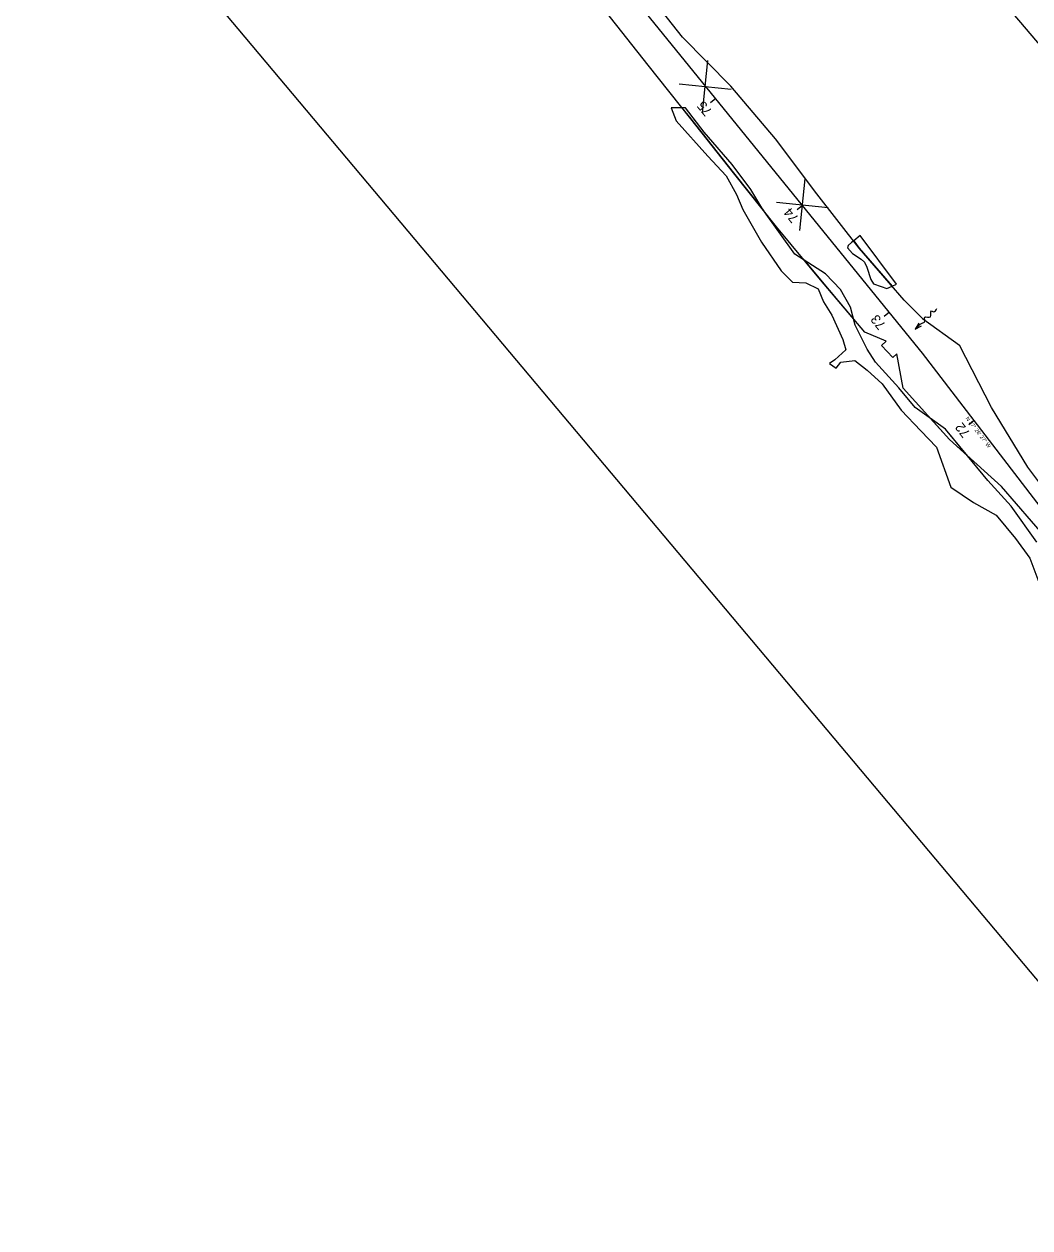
# Model space of a CAD drawing. Extents: x 2399886 to 2513208, y 556821 to 592417.
# Drawn here: x 2441599 to 2442329, y 558741 to 559616 of the extents above; entities that cross this region are included whole.
import ezdxf

# ---------------------------------------------------------------- set-up
doc = ezdxf.new("R2010")
doc.units = 0
for name, color, linetype in [('DR_X_Flow_Arrow', 7, 'Continuous'), ('EV_Ecological_Wetlands', 7, 'Continuous'), ('GE_P_CL_20', 7, 'Continuous'), ('GE_P_CL_50', 7, 'Continuous'), ('GK_Visualization', 7, 'Continuous'), ('RW_P_Const_Limits', 7, 'Continuous'), ('SC_Scratch1', 7, 'Continuous'), ('VG_P_Cells', 7, 'Continuous')]:
    doc.layers.add(name, color=color, linetype=linetype)

msp = doc.modelspace()

# ---------------------------------------------------------------- linework, layer by layer
at = {"layer": 'DR_X_Flow_Arrow'}
for p, q in [((2442248.55, 559398.66), (2442245.88, 559394.22)), ((2442245.88, 559394.22), (2442250.41, 559396.73))]:
    msp.add_line(p, q, dxfattribs=at)
msp.add_spline([(2442245.88, 559394.22), (2442249.63, 559397.82), (2442251.44, 559398.91), (2442252.69, 559399.48), (2442253.01, 559402.98), (2442256.98, 559403.22), (2442257.71, 559407.51), (2442259.19, 559406.99), (2442261.63, 559409.4)], degree=3, dxfattribs=at)
at = {"layer": 'EV_Ecological_Wetlands'}
for p, q in [((2442079.15, 559555.14), (2442076.52, 559555.14)), ((2442076.52, 559555.14), (2442082.93, 559547.05)), ((2442082.93, 559547.05), (2442114, 559507.87)), ((2442114, 559507.87), (2442135.71, 559480.56)), ((2442135.71, 559480.56), (2442135.14, 559481.36)), ((2442201.28, 559458.48), (2442199.74, 559457.2)), ((2442205.36, 559453.24), (2442201.28, 559458.48)), ((2442201.28, 559458.48), (2442205.36, 559453.24)), ((2442229.23, 559425.55), (2442205.36, 559453.24)), ((2442205.36, 559453.24), (2442229.23, 559425.55)), ((2442180.71, 559434.48), (2442165.21, 559444.52)), ((2442165.21, 559444.52), (2442177.05, 559430.25)), ((2442177.05, 559430.25), (2442201.23, 559401.59)), ((2442229.23, 559425.55), (2442232.39, 559426.94)), ((2442201.23, 559401.59), (2442198.94, 559410.18)), ((2442267.95, 559321.64), (2442256.83, 559329.49)), ((2442256.83, 559329.49), (2442270.76, 559313.99)), ((2442284.19, 559301.98), (2442267.95, 559321.64)), ((2442270.76, 559313.99), (2442284.19, 559301.98))]:
    msp.add_line(p, q, dxfattribs=at)
for points in [[(2442334.36, 559239.6), (2442315.7, 559265.65), (2442298.77, 559284.31), (2442267.95, 559321.64), (2442245.82, 559337.26), (2442234.1, 559351.58), (2442217.17, 559370.25), (2442211.1, 559379.8), (2442202.42, 559397.16), (2442198.94, 559410.18), (2442191.57, 559423.2), (2442180.71, 559434.48), (2442158.58, 559448.81), (2442135.14, 559481.36), (2442126.46, 559495.68), (2442113.01, 559513.91), (2442092.61, 559537.35), (2442079.15, 559555.14), (2442068.74, 559555.14), (2442072.21, 559545.59), (2442095.21, 559519.99), (2442108.67, 559505.66), (2442116.04, 559492.21), (2442120.82, 559481.36), (2442134.27, 559457.49), (2442148.6, 559436.65), (2442156.84, 559428.41), (2442166.39, 559427.97), (2442175.51, 559423.63), (2442179.41, 559414.08), (2442185.49, 559404.53), (2442193.3, 559386.74), (2442195.47, 559379.36), (2442187.66, 559371.98), (2442183.75, 559369.38), (2442188.53, 559365.91), (2442192, 559370.25), (2442201.98, 559371.55), (2442211.1, 559364.6), (2442221.95, 559354.62), (2442235.84, 559335.52), (2442250.16, 559320.33), (2442261.44, 559308.61), (2442271.86, 559279.53), (2442288.35, 559268.25), (2442304.85, 559259.14), (2442318.74, 559242.21), (2442329.15, 559227.89), (2442335.66, 559210.52)], [(2442113.01, 559513.91), (2442092.61, 559537.35), (2442079.15, 559555.14)], [(2442135.14, 559481.36), (2442126.46, 559495.68), (2442113.01, 559513.91)], [(2442232.39, 559426.94), (2442205.91, 559462.31), (2442201.28, 559458.48)], [(2442199.74, 559457.2), (2442197.13, 559455.14), (2442196.7, 559453.3), (2442200.28, 559449.28), (2442206.79, 559445.16), (2442209.18, 559442.88), (2442210.7, 559439.41), (2442213.63, 559430.4), (2442215.58, 559427.15), (2442221.22, 559425.19), (2442225.45, 559423.89), (2442229.23, 559425.55)], [(2442198.94, 559410.18), (2442191.57, 559423.2), (2442180.71, 559434.48)]]:
    msp.add_lwpolyline(points, dxfattribs=at)
at = {"layer": 'GE_P_CL_20'}
for p, q in [((2442251.31, 559376.86), (2441754.32, 559988.88)), ((2442339.87, 559261.21), (2442251.31, 559376.86))]:
    msp.add_line(p, q, dxfattribs=at)
at = {"layer": 'GE_P_CL_50'}
for p, q in [((2442251.31, 559376.86), (2441754.32, 559988.88)), ((2442101.12, 559561.82), (2442097.24, 559558.67)), ((2442164.16, 559484.19), (2442160.28, 559481.04)), ((2442227.2, 559406.56), (2442223.31, 559403.41)), ((2442339.87, 559261.21), (2442251.31, 559376.86)), ((2442288.85, 559327.84), (2442284.88, 559324.8))]:
    msp.add_line(p, q, dxfattribs=at)
at = {"layer": 'GK_Visualization'}
for p, q in [((2442251.31, 559376.86), (2441754.32, 559988.88)), ((2442251.25, 559376.8), (2442251.38, 559376.93)), ((2442251.25, 559376.93), (2442251.38, 559376.8)), ((2442339.87, 559261.21), (2442251.31, 559376.86))]:
    msp.add_line(p, q, dxfattribs=at)
at = {"layer": 'RW_P_Const_Limits'}
for p, q in [((2442076.84, 559606.51), (2442045.87, 559645.77)), ((2442051.88, 559586.24), (2442020.84, 559625.44)), ((2442112.1, 559570.74), (2442076.84, 559606.51)), ((2442082.93, 559547.05), (2442051.88, 559586.24)), ((2442144.39, 559532.55), (2442112.1, 559570.74)), ((2442114, 559507.87), (2442082.93, 559547.05)), ((2442174.58, 559492.66), (2442144.39, 559532.55)), ((2442145.12, 559468.73), (2442114, 559507.87)), ((2442205.36, 559453.24), (2442174.58, 559492.66)), ((2442177.05, 559430.25), (2442145.12, 559468.73)), ((2442238.02, 559415.35), (2442205.36, 559453.24)), ((2442209.3, 559392.03), (2442177.05, 559430.25)), ((2442238.02, 559415.35), (2442250.47, 559402.71)), ((2442250.47, 559402.71), (2442251.17, 559401.99)), ((2442251.17, 559401.99), (2442278.14, 559382.62)), ((2442224.77, 559385.59), (2442209.3, 559392.03)), ((2442224.77, 559385.59), (2442221.41, 559382.36)), ((2442221.41, 559382.36), (2442229.74, 559373.72)), ((2442301.29, 559337.37), (2442278.14, 559382.62)), ((2442278.14, 559382.62), (2442278.14, 559382.62)), ((2442229.74, 559373.72), (2442232.55, 559376.43)), ((2442237.23, 559351.29), (2442232.55, 559376.43)), ((2442270.76, 559313.99), (2442237.23, 559351.29)), ((2442327.7, 559293.92), (2442301.29, 559337.37)), ((2442308.68, 559280.05), (2442270.76, 559313.99)), ((2442357.37, 559254.36), (2442327.7, 559293.92)), ((2442341.31, 559242.06), (2442308.68, 559280.05))]:
    msp.add_line(p, q, dxfattribs=at)
at = {"layer": 'SC_Scratch1'}
for p, q in [((2442855.88, 558982.28), (2441938.96, 560074.24)), ((2442485.78, 558741.19), (2441598.55, 559797.8))]:
    msp.add_line(p, q, dxfattribs=at)
at = {"layer": 'VG_P_Cells'}
for p, q in [((2442091.39, 559551.81), (2442095.29, 559589.41)), ((2442074.54, 559572.56), (2442112.14, 559568.66)), ((2442093.34, 559570.6), (2442093.34, 559570.6)), ((2442162.05, 559465.91), (2442165.95, 559503.51)), ((2442145.2, 559486.66), (2442182.8, 559482.76)), ((2442164, 559484.71), (2442164, 559484.71))]:
    msp.add_line(p, q, dxfattribs=at)

# ---------------------------------------------------------------- texts
at = {"layer": 'GE_P_CL_20'}
msp.add_text('N 37%%d 26\' 27" W', height=2.8, rotation=307.44097, dxfattribs=at).set_placement((2442282.38, 559329.38))
at = {"layer": 'GE_P_CL_50'}
for s, rotation, p in [('75', 129.07875, (2442098.86, 559552.7)), ('74', 129.07875, (2442161.84, 559475.14)), ('73', 129.07875, (2442224.95, 559397.43)), ('72', 127.44097, (2442286.29, 559318.84))]:
    msp.add_text(s, height=7, rotation=rotation, dxfattribs=at).set_placement(p)
at = {"layer": 'GK_Visualization'}
msp.add_text('TEMPF12', height=0.14, dxfattribs=at).set_placement((2442250.53, 559376.86))

doc.saveas('drawing.dxf')
